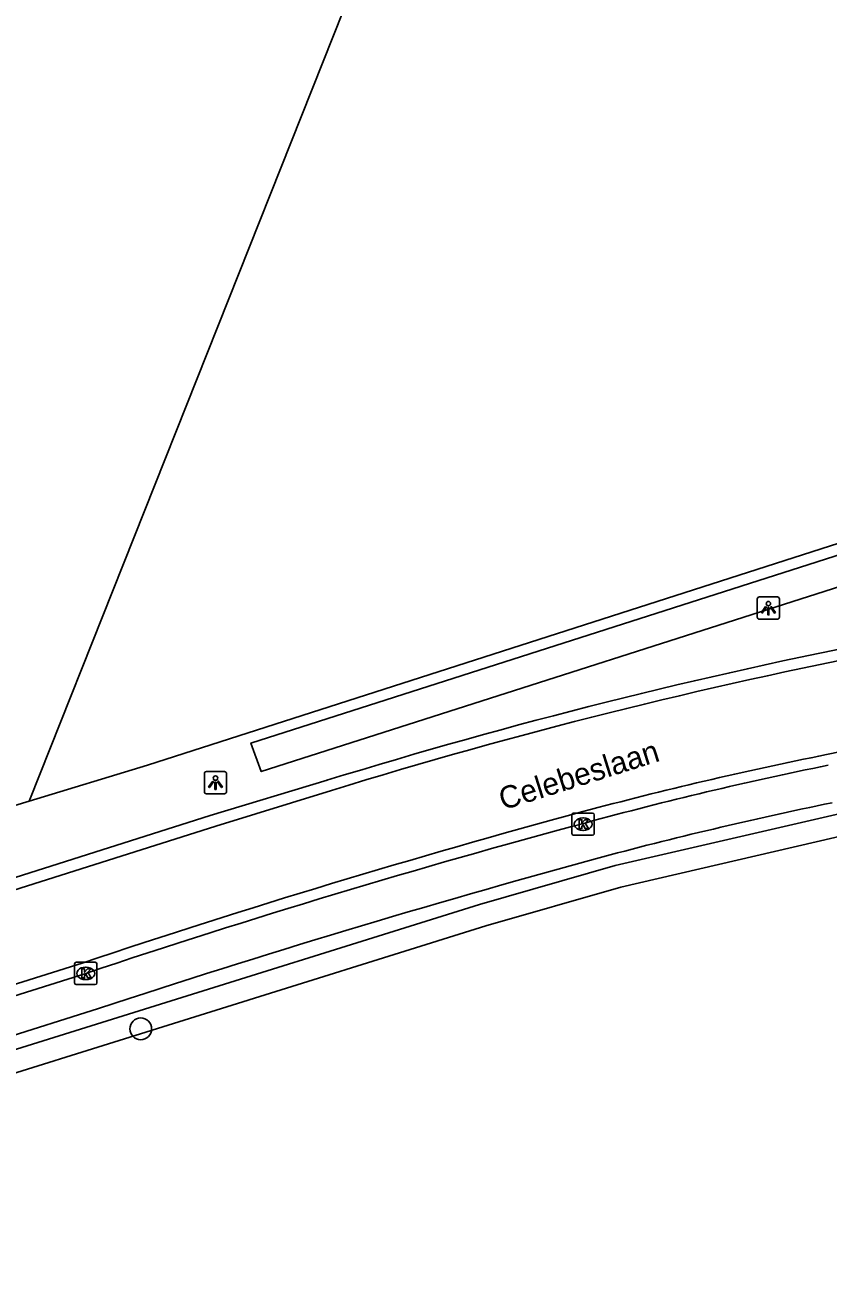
# Model space of a CAD drawing. Extents: x 162880 to 165536, y 384011 to 385179.
# Drawn here: x 163777.7 to 163813.7, y 384503.4 to 384559.2 of the extents above; entities that cross this region are included whole.
import ezdxf

# ---------------------------------------------------------------- set-up
doc = ezdxf.new("R2010")
doc.units = 0
for name, color, linetype in [('IMGEO_Boom', 7, 'Continuous'), ('IMGEO_Bouwland', 7, 'Continuous'), ('IMGEO_Groenvoorziening', 7, 'Continuous'), ('IMGEO_Haag', 7, 'Continuous'), ('IMGEO_Kolk', 7, 'Continuous'), ('IMGEO_Lichtpunt', 7, 'Continuous'), ('IMGEO_Openbare_ruimte_label', 7, 'Continuous'), ('IMGEO_Rijbaan_lokaal_gesloten', 7, 'Continuous'), ('IMGEO_Rijbaan_lokaal_open', 7, 'Continuous'), ('IMGEO_Voetpad_open', 7, 'Continuous'), ('IMGEO_Waterloop', 7, 'Continuous')]:
    doc.layers.add(name, color=color, linetype=linetype)

msp = doc.modelspace()

# ---------------------------------------------------------------- linework, layer by layer
at = {"layer": 'IMGEO_Boom'}
msp.add_circle((163782.86, 384514.184), 0.489, dxfattribs=at)
at = {"layer": 'IMGEO_Bouwland'}
for points in [[(163777.851, 384524.403), (163799.02, 384577.651)], [(163856.415, 384552.055), (163855.609, 384549.273), (163851.342, 384547.903), (163783.168, 384526.014), (163777.851, 384524.403)]]:
    msp.add_lwpolyline(points, dxfattribs=at)
at = {"layer": 'IMGEO_Groenvoorziening'}
msp.add_lwpolyline([(163777.851, 384524.403), (163752.269, 384516.65), (163768.498, 384570.754)], dxfattribs=at)
at = {"layer": 'IMGEO_Haag'}
for points in [[(163772.691, 384510.794), (163748.898, 384503.363), (163748.645, 384504.331), (163798.055, 384519.764), (163804.144, 384521.512), (163814.635, 384523.939), (163855.656, 384532.338)], [(163772.691, 384510.794), (163798.342, 384518.806), (163804.4, 384520.545), (163814.844, 384522.961), (163855.899, 384531.368)]]:
    msp.add_lwpolyline(points, dxfattribs=at)
at = {"layer": 'IMGEO_Kolk'}
for p, q in [((163802.207, 384522.943), (163802.207, 384523.795)), ((163802.282, 384523.869), (163803.134, 384523.869)), ((163802.695, 384523.649), (163802.72, 384523.649)), ((163803.208, 384523.795), (163803.208, 384522.943)), ((163803.134, 384522.869), (163802.282, 384522.869)), ((163802.718, 384523.089), (163802.693, 384523.089)), ((163779.893, 384516.248), (163779.893, 384517.1)), ((163779.968, 384517.174), (163780.82, 384517.174)), ((163780.381, 384516.954), (163780.406, 384516.954)), ((163780.894, 384517.1), (163780.894, 384516.248)), ((163780.82, 384516.174), (163779.968, 384516.174)), ((163780.404, 384516.394), (163780.379, 384516.394))]:
    msp.add_line(p, q, dxfattribs=at)
for points in [[(163802.207, 384522.943), (163802.207, 384523.795)], [(163802.282, 384523.869), (163803.134, 384523.869)], [(163802.528, 384523.569), (163802.651, 384523.569), (163802.651, 384523.418), (163802.781, 384523.569), (163802.945, 384523.569), (163802.799, 384523.418), (163802.952, 384523.169), (163802.8, 384523.169), (163802.715, 384523.333), (163802.651, 384523.266), (163802.651, 384523.169), (163802.528, 384523.169), (163802.528, 384523.569)], [(163803.208, 384523.795), (163803.208, 384522.943)], [(163803.134, 384522.869), (163802.282, 384522.869)], [(163779.893, 384516.248), (163779.893, 384517.1)], [(163779.968, 384517.174), (163780.82, 384517.174)], [(163780.214, 384516.874), (163780.337, 384516.874), (163780.337, 384516.723), (163780.467, 384516.874), (163780.631, 384516.874), (163780.485, 384516.723), (163780.638, 384516.474), (163780.486, 384516.474), (163780.401, 384516.638), (163780.337, 384516.571), (163780.337, 384516.474), (163780.214, 384516.474), (163780.214, 384516.874)], [(163780.894, 384517.1), (163780.894, 384516.248)], [(163780.82, 384516.174), (163779.968, 384516.174)]]:
    msp.add_lwpolyline(points, dxfattribs=at)
for centre, start, end in [((163802.284, 384523.793), 91.552, 178.448), ((163802.284, 384523.793), 91.552, 178.448), ((163803.132, 384523.793), 1.552, 88.448), ((163803.132, 384523.793), 1.552, 88.448), ((163802.284, 384522.945), 181.552, 268.448), ((163802.284, 384522.945), 181.552, 268.448), ((163803.132, 384522.945), 271.552, 358.448), ((163803.132, 384522.945), 271.552, 358.448), ((163779.97, 384517.098), 91.552, 178.448), ((163779.97, 384517.098), 91.552, 178.448), ((163780.818, 384517.098), 1.552, 88.448), ((163780.818, 384517.098), 1.552, 88.448), ((163779.97, 384516.25), 181.552, 268.448), ((163779.97, 384516.25), 181.552, 268.448), ((163780.818, 384516.25), 271.552, 358.448), ((163780.818, 384516.25), 271.552, 358.448)]:
    msp.add_arc(centre, 0.0765, start, end, dxfattribs=at)
for centre, major_axis, ratio, start_param, end_param in [((163802.694, 384523.369), (-0.387, 0.002), 0.722429, 4.712389, 7.853982), ((163802.719, 384523.369), (-0.39, 0.002), 0.717154, 1.570796, 4.712389), ((163780.38, 384516.674), (-0.387, 0.002), 0.722429, 4.712389, 7.853982), ((163780.405, 384516.674), (-0.39, 0.002), 0.717154, 1.570796, 4.712389)]:
    msp.add_ellipse(centre, major_axis=major_axis, ratio=ratio, start_param=start_param, end_param=end_param, dxfattribs=at)
at = {"layer": 'IMGEO_Lichtpunt'}
for p, q in [((163810.52, 384533.466), (163810.52, 384532.659)), ((163810.52, 384533.466), (163810.52, 384532.659)), ((163811.422, 384533.561), (163810.614, 384533.561)), ((163811.422, 384533.561), (163810.614, 384533.561)), ((163811.516, 384532.659), (163811.516, 384533.466)), ((163811.516, 384532.659), (163811.516, 384533.466)), ((163810.614, 384532.565), (163811.422, 384532.565)), ((163810.614, 384532.565), (163811.422, 384532.565)), ((163785.715, 384525.637), (163785.715, 384524.83)), ((163785.715, 384525.637), (163785.715, 384524.83)), ((163786.617, 384525.732), (163785.809, 384525.732)), ((163786.617, 384525.732), (163785.809, 384525.732)), ((163786.711, 384524.83), (163786.711, 384525.637)), ((163786.711, 384524.83), (163786.711, 384525.637)), ((163785.809, 384524.736), (163786.617, 384524.736)), ((163785.809, 384524.736), (163786.617, 384524.736))]:
    msp.add_line(p, q, dxfattribs=at)
for points in [[(163810.894, 384533.13), (163810.933, 384533.102), (163810.745, 384532.84), (163810.707, 384532.867), (163810.894, 384533.13)], [(163810.996, 384533.082), (163811.043, 384533.082), (163811.043, 384532.76), (163810.996, 384532.76), (163810.996, 384533.082)], [(163811.106, 384533.102), (163811.144, 384533.129), (163811.331, 384532.867), (163811.292, 384532.839), (163811.106, 384533.102)], [(163786.089, 384525.301), (163786.128, 384525.273), (163785.94, 384525.011), (163785.902, 384525.038), (163786.089, 384525.301)], [(163786.191, 384525.253), (163786.238, 384525.253), (163786.238, 384524.931), (163786.191, 384524.931), (163786.191, 384525.253)], [(163786.301, 384525.273), (163786.339, 384525.3), (163786.526, 384525.038), (163786.487, 384525.01), (163786.301, 384525.273)]]:
    msp.add_lwpolyline(points, dxfattribs=at)
for centre in [(163811.019, 384533.264), (163786.214, 384525.435)]:
    msp.add_circle(centre, 0.0994, dxfattribs=at)
for centre, start, end in [((163810.614, 384533.466), 90, 180), ((163810.614, 384533.466), 90, 180), ((163811.422, 384533.466), 0, 90), ((163811.422, 384533.466), 0, 90), ((163810.614, 384532.659), 180, 270), ((163810.614, 384532.659), 180, 270), ((163811.422, 384532.659), 270, 0), ((163811.422, 384532.659), 270, 360), ((163785.809, 384525.637), 90, 180), ((163785.809, 384525.637), 90, 180), ((163786.617, 384525.637), 0, 90), ((163786.617, 384525.637), 0, 90), ((163785.809, 384524.83), 180, 270), ((163785.809, 384524.83), 180, 270), ((163786.617, 384524.83), 270, 0), ((163786.617, 384524.83), 270, 360)]:
    msp.add_arc(centre, 0.0946, start, end, dxfattribs=at)
at = {"layer": 'IMGEO_Rijbaan_lokaal_gesloten'}
for points in [[(163854.265, 384534.797), (163813.623, 384526.49)], [(163755.965, 384513.688), (163786.222, 384523.282), (163791.418, 384524.876)], [(163780.232, 384517.137), (163757.115, 384509.864)]]:
    msp.add_lwpolyline(points, dxfattribs=at)
for centre, radius, start, end in [((163860.181, 384303.495), 231.815, 100.85578, 107.25537), ((163848.226, 384353.977), 175.949, 101.34183, 104.99714), ((163906.967, 384138.759), 399.038, 105.14766, 108.51787)]:
    msp.add_arc(centre, radius, start, end, dxfattribs=at)
at = {"layer": 'IMGEO_Rijbaan_lokaal_open'}
for points in [[(163791.216, 384525.336), (163785.969, 384523.751), (163755.812, 384514.166), (163753.158, 384513.373), (163752.94, 384513.318)], [(163746.591, 384506.492), (163755.421, 384508.79), (163759.947, 384510.236), (163780.394, 384516.674)]]:
    msp.add_lwpolyline(points, dxfattribs=at)
for centre, radius, start, end in [((163863.124, 384292.512), 243.676, 101.04373, 107.16337), ((163846.419, 384364.045), 165.24, 101.42164, 105.29055), ((163902.592, 384151.638), 384.946, 105.01806, 108.50823)]:
    msp.add_arc(centre, radius, start, end, dxfattribs=at)
at = {"layer": 'IMGEO_Voetpad_open'}
msp.add_lwpolyline([(163743.651, 384504.054), (163756.083, 384507.235), (163758.748, 384508.071), (163780.96, 384515.1)], dxfattribs=at)
for centre, radius, start, end in [((163850.413, 384346.41), 181.632, 101.60467, 105.046), ((163925.408, 384075.814), 462.426, 105.31601, 108.20217)]:
    msp.add_arc(centre, radius, start, end, dxfattribs=at)
at = {"layer": 'IMGEO_Waterloop'}
msp.add_lwpolyline([(163851.126, 384547.282), (163857.472, 384549.314), (163857.923, 384548.005), (163850.558, 384545.649), (163788.264, 384525.725), (163787.802, 384527.004), (163851.126, 384547.282)], dxfattribs=at)

# ---------------------------------------------------------------- texts
at = {"layer": 'IMGEO_Openbare_ruimte_label'}
msp.add_text('Celebeslaan', height=1, rotation=17.4566, dxfattribs=at).set_placement((163799.116, 384523.988))

doc.saveas('drawing.dxf')
